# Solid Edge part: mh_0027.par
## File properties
Title: spring
Author: edge
Template: normal.par
Last saved by: edge
Revision: 37
Application: Solid Edge
Density: 0.001200 g/mm^3
Accuracy: 0.99
非切断部品: False
文書内容のタイプ: 0
Material: ABS
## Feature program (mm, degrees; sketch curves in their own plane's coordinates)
sketch for "unnamed Protrusion 1" plane through (0, 0, 0) normal (0, 0, 1) x-axis (1, 0, 0)
  line (-30, 65) -> (30, 65)
  line (30, 65) -> (30, -15)
  line (30, -15) -> (-30, -15)
  line (-30, -15) -> (-30, 65)
extrude "unnamed Protrusion 1" add finite 26 along +normal
thinwall "Thinwall_1"  Thickness = 1 mm
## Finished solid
Body 1: solid body, 11 faces, 24 edges, 16 vertices.
  Faces by surface: plane 11
  Edges by curve: line 24
Bounding box of the edges (mm): 60.000 x 80.000 x 26.000, from (-30, -15, 0) to (30, 65, 26).
Planar faces by outward normal: +x 2, +y 2, +z 1, -x 2, -y 2, -z 2
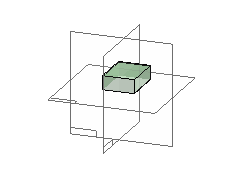
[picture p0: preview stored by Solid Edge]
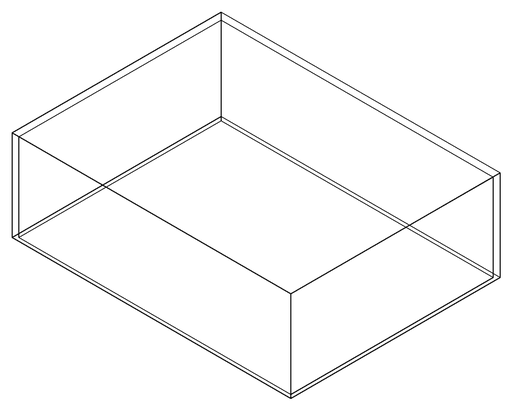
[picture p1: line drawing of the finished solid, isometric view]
